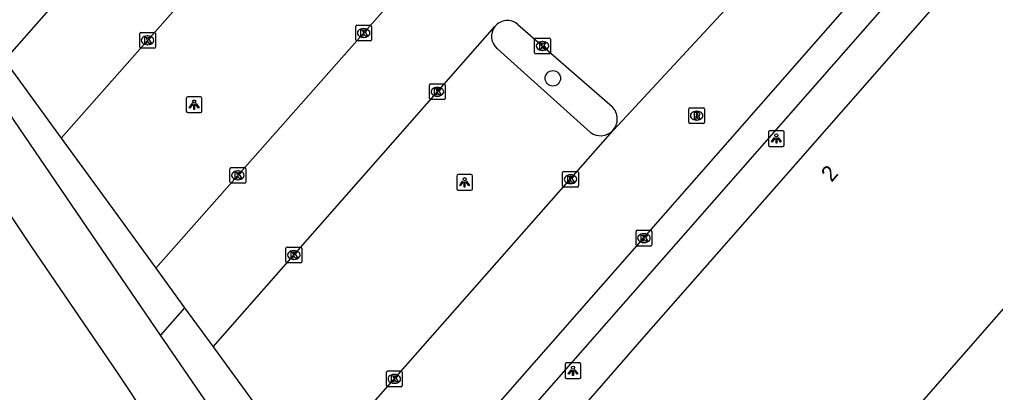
# Model space of a CAD drawing. Extents: x 158474 to 159560, y 388525 to 389605.
# Drawn here: x 158694.2 to 158756.2, y 388754.6 to 388778.3 of the extents above; entities that cross this region are included whole.
import ezdxf

# ---------------------------------------------------------------- set-up
doc = ezdxf.new("R2010")
doc.units = 0
for name, color, linetype in [('IMGEO_Boom', 7, 'Continuous'), ('IMGEO_Groenvoorziening', 7, 'Continuous'), ('IMGEO_Kolk', 7, 'Continuous'), ('IMGEO_Lichtpunt', 7, 'Continuous'), ('IMGEO_Meer_plas_ven_vijver', 7, 'Continuous'), ('IMGEO_Pand', 7, 'Continuous'), ('IMGEO_Pand_nummerreeks', 7, 'Continuous'), ('IMGEO_Parkeervlak_open', 7, 'Continuous'), ('IMGEO_Rijbaan_lokaal_open', 7, 'Continuous'), ('IMGEO_Rioolput', 7, 'Continuous'), ('IMGEO_Voetpad_open', 7, 'Continuous'), ('IMGEO_Walbescherming', 7, 'Continuous')]:
    doc.layers.add(name, color=color, linetype=linetype)

msp = doc.modelspace()

# ---------------------------------------------------------------- linework, layer by layer
at = {"layer": 'IMGEO_Boom'}
msp.add_circle((158728.062, 388774.565), 0.489, dxfattribs=at)
at = {"layer": 'IMGEO_Groenvoorziening'}
for points in [[(158703.128, 388758.224), (158699.444, 388763.626), (158691.492, 388775.285), (158687.327, 388781.391), (158681.382, 388789.641), (158676.637, 388797.026), (158667.372, 388809.99), (158665.283, 388814.769), (158660.005, 388821.203), (158657.276, 388822.984), (158656.805, 388823.409), (158654.184, 388825.806)], [(158704.66, 388759.967), (158703.128, 388758.224)], [(158714.762, 388744.037), (158714.238, 388744.412), (158711.437, 388746.785), (158708.904, 388750), (158707.649, 388751.593), (158703.128, 388758.224)]]:
    msp.add_lwpolyline(points, dxfattribs=at)
at = {"layer": 'IMGEO_Kolk'}
for p, q in [((158715.537, 388777.02), (158715.537, 388777.872)), ((158715.612, 388777.946), (158716.464, 388777.946)), ((158716.538, 388777.872), (158716.538, 388777.02)), ((158701.801, 388776.555), (158701.801, 388777.407)), ((158701.876, 388777.481), (158702.728, 388777.481)), ((158702.289, 388777.261), (158702.314, 388777.261)), ((158702.802, 388777.407), (158702.802, 388776.555)), ((158716.025, 388777.726), (158716.05, 388777.726)), ((158702.312, 388776.701), (158702.287, 388776.701)), ((158716.464, 388776.946), (158715.612, 388776.946)), ((158716.048, 388777.166), (158716.023, 388777.166)), ((158726.905, 388776.195), (158726.905, 388777.047)), ((158726.98, 388777.121), (158727.832, 388777.121)), ((158727.393, 388776.901), (158727.418, 388776.901)), ((158727.906, 388777.047), (158727.906, 388776.195)), ((158702.728, 388776.481), (158701.876, 388776.481)), ((158727.832, 388776.121), (158726.98, 388776.121)), ((158727.416, 388776.341), (158727.391, 388776.341)), ((158720.226, 388773.283), (158720.226, 388774.135)), ((158720.301, 388774.209), (158721.153, 388774.209)), ((158721.227, 388774.135), (158721.227, 388773.283)), ((158720.714, 388773.989), (158720.739, 388773.989)), ((158721.153, 388773.209), (158720.301, 388773.209)), ((158720.737, 388773.429), (158720.712, 388773.429)), ((158707.542, 388767.962), (158707.542, 388768.814)), ((158707.617, 388768.888), (158708.469, 388768.888)), ((158708.03, 388768.668), (158708.055, 388768.668)), ((158708.543, 388768.814), (158708.543, 388767.962)), ((158728.684, 388767.717), (158728.684, 388768.569)), ((158728.759, 388768.643), (158729.611, 388768.643)), ((158729.685, 388768.569), (158729.685, 388767.717)), ((158708.469, 388767.888), (158707.617, 388767.888)), ((158708.053, 388768.108), (158708.028, 388768.108)), ((158729.172, 388768.423), (158729.197, 388768.423)), ((158729.611, 388767.643), (158728.759, 388767.643)), ((158729.195, 388767.863), (158729.17, 388767.863)), ((158733.351, 388763.968), (158733.351, 388764.82)), ((158733.426, 388764.894), (158734.278, 388764.894)), ((158734.352, 388764.82), (158734.352, 388763.968)), ((158733.839, 388764.674), (158733.864, 388764.674)), ((158711.099, 388762.894), (158711.099, 388763.746)), ((158711.174, 388763.82), (158712.026, 388763.82)), ((158711.587, 388763.6), (158711.612, 388763.6)), ((158712.1, 388763.746), (158712.1, 388762.894)), ((158734.278, 388763.894), (158733.426, 388763.894)), ((158733.862, 388764.114), (158733.837, 388764.114)), ((158711.61, 388763.04), (158711.585, 388763.04)), ((158712.026, 388762.82), (158711.174, 388762.82)), ((158717.485, 388755.014), (158717.485, 388755.866)), ((158717.56, 388755.94), (158718.412, 388755.94)), ((158717.973, 388755.72), (158717.998, 388755.72)), ((158718.486, 388755.866), (158718.486, 388755.014)), ((158718.412, 388754.94), (158717.56, 388754.94)), ((158717.996, 388755.16), (158717.971, 388755.16))]:
    msp.add_line(p, q, dxfattribs=at)
for points in [[(158715.537, 388777.02), (158715.537, 388777.872)], [(158715.612, 388777.946), (158716.464, 388777.946)], [(158716.538, 388777.872), (158716.538, 388777.02)], [(158701.801, 388776.555), (158701.801, 388777.407)], [(158701.876, 388777.481), (158702.728, 388777.481)], [(158702.122, 388777.181), (158702.245, 388777.181), (158702.245, 388777.03), (158702.375, 388777.181), (158702.539, 388777.181), (158702.393, 388777.03), (158702.546, 388776.781), (158702.394, 388776.781), (158702.309, 388776.945), (158702.245, 388776.878), (158702.245, 388776.781), (158702.122, 388776.781), (158702.122, 388777.181)], [(158702.802, 388777.407), (158702.802, 388776.555)], [(158715.858, 388777.646), (158715.981, 388777.646), (158715.981, 388777.495), (158716.111, 388777.646), (158716.275, 388777.646), (158716.129, 388777.495), (158716.282, 388777.246), (158716.13, 388777.246), (158716.045, 388777.41), (158715.981, 388777.343), (158715.981, 388777.246), (158715.858, 388777.246), (158715.858, 388777.646)], [(158716.464, 388776.946), (158715.612, 388776.946)], [(158726.905, 388776.195), (158726.905, 388777.047)], [(158726.98, 388777.121), (158727.832, 388777.121)], [(158727.226, 388776.821), (158727.349, 388776.821), (158727.349, 388776.67), (158727.479, 388776.821), (158727.643, 388776.821), (158727.497, 388776.67), (158727.65, 388776.421), (158727.498, 388776.421), (158727.413, 388776.585), (158727.349, 388776.518), (158727.349, 388776.421), (158727.226, 388776.421), (158727.226, 388776.821)], [(158727.906, 388777.047), (158727.906, 388776.195)], [(158702.728, 388776.481), (158701.876, 388776.481)], [(158727.832, 388776.121), (158726.98, 388776.121)], [(158720.226, 388773.283), (158720.226, 388774.135)], [(158720.301, 388774.209), (158721.153, 388774.209)], [(158721.227, 388774.135), (158721.227, 388773.283)], [(158720.547, 388773.909), (158720.67, 388773.909), (158720.67, 388773.758), (158720.8, 388773.909), (158720.964, 388773.909), (158720.818, 388773.758), (158720.971, 388773.509), (158720.819, 388773.509), (158720.734, 388773.673), (158720.67, 388773.606), (158720.67, 388773.509), (158720.547, 388773.509), (158720.547, 388773.909)], [(158721.153, 388773.209), (158720.301, 388773.209)], [(158707.542, 388767.962), (158707.542, 388768.814)], [(158707.617, 388768.888), (158708.469, 388768.888)], [(158707.863, 388768.588), (158707.986, 388768.588), (158707.986, 388768.437), (158708.116, 388768.588), (158708.28, 388768.588), (158708.134, 388768.437), (158708.287, 388768.188), (158708.135, 388768.188), (158708.05, 388768.352), (158707.986, 388768.285), (158707.986, 388768.188), (158707.863, 388768.188), (158707.863, 388768.588)], [(158708.543, 388768.814), (158708.543, 388767.962)], [(158728.684, 388767.717), (158728.684, 388768.569)], [(158728.759, 388768.643), (158729.611, 388768.643)], [(158729.685, 388768.569), (158729.685, 388767.717)], [(158708.469, 388767.888), (158707.617, 388767.888)], [(158729.005, 388768.343), (158729.128, 388768.343), (158729.128, 388768.192), (158729.258, 388768.343), (158729.422, 388768.343), (158729.276, 388768.192), (158729.429, 388767.943), (158729.277, 388767.943), (158729.192, 388768.107), (158729.128, 388768.04), (158729.128, 388767.943), (158729.005, 388767.943), (158729.005, 388768.343)], [(158729.611, 388767.643), (158728.759, 388767.643)], [(158733.351, 388763.968), (158733.351, 388764.82)], [(158733.426, 388764.894), (158734.278, 388764.894)], [(158734.352, 388764.82), (158734.352, 388763.968)], [(158733.672, 388764.594), (158733.795, 388764.594), (158733.795, 388764.443), (158733.925, 388764.594), (158734.089, 388764.594), (158733.943, 388764.443), (158734.096, 388764.194), (158733.944, 388764.194), (158733.859, 388764.358), (158733.795, 388764.291), (158733.795, 388764.194), (158733.672, 388764.194), (158733.672, 388764.594)], [(158711.099, 388762.894), (158711.099, 388763.746)], [(158711.174, 388763.82), (158712.026, 388763.82)], [(158712.1, 388763.746), (158712.1, 388762.894)], [(158734.278, 388763.894), (158733.426, 388763.894)], [(158711.42, 388763.52), (158711.543, 388763.52), (158711.543, 388763.369), (158711.673, 388763.52), (158711.837, 388763.52), (158711.691, 388763.369), (158711.844, 388763.12), (158711.692, 388763.12), (158711.607, 388763.284), (158711.543, 388763.217), (158711.543, 388763.12), (158711.42, 388763.12), (158711.42, 388763.52)], [(158712.026, 388762.82), (158711.174, 388762.82)], [(158717.485, 388755.014), (158717.485, 388755.866)], [(158717.56, 388755.94), (158718.412, 388755.94)], [(158717.806, 388755.64), (158717.929, 388755.64), (158717.929, 388755.489), (158718.059, 388755.64), (158718.223, 388755.64), (158718.077, 388755.489), (158718.23, 388755.24), (158718.078, 388755.24), (158717.993, 388755.404), (158717.929, 388755.337), (158717.929, 388755.24), (158717.806, 388755.24), (158717.806, 388755.64)], [(158718.486, 388755.866), (158718.486, 388755.014)], [(158718.412, 388754.94), (158717.56, 388754.94)]]:
    msp.add_lwpolyline(points, dxfattribs=at)
for centre, start, end in [((158715.614, 388777.87), 91.55205, 178.44795), ((158715.614, 388777.87), 91.55205, 178.44795), ((158716.462, 388777.87), 1.55205, 88.44795), ((158716.462, 388777.87), 1.55205, 88.44795), ((158701.878, 388777.405), 91.55205, 178.44795), ((158701.878, 388777.405), 91.55205, 178.44795), ((158702.726, 388777.405), 1.55205, 88.44795), ((158702.726, 388777.405), 1.55205, 88.44795), ((158701.878, 388776.557), 181.55205, 268.44795), ((158701.878, 388776.557), 181.55205, 268.44795), ((158702.726, 388776.557), 271.55205, 358.44795), ((158702.726, 388776.557), 271.55205, 358.44795), ((158715.614, 388777.022), 181.55205, 268.44795), ((158715.614, 388777.022), 181.55205, 268.44795), ((158716.462, 388777.022), 271.55205, 358.44795), ((158716.462, 388777.022), 271.55205, 358.44795), ((158726.982, 388777.045), 91.55205, 178.44795), ((158726.982, 388777.045), 91.55205, 178.44795), ((158727.83, 388777.045), 1.55205, 88.44795), ((158727.83, 388777.045), 1.55205, 88.44795), ((158726.982, 388776.197), 181.55205, 268.44795), ((158726.982, 388776.197), 181.55205, 268.44795), ((158727.83, 388776.197), 271.55205, 358.44795), ((158727.83, 388776.197), 271.55205, 358.44795), ((158720.303, 388774.133), 91.55205, 178.44795), ((158720.303, 388774.133), 91.55205, 178.44795), ((158721.151, 388774.133), 1.55205, 88.44795), ((158721.151, 388774.133), 1.55205, 88.44795), ((158720.303, 388773.285), 181.55205, 268.44795), ((158720.303, 388773.285), 181.55205, 268.44795), ((158721.151, 388773.285), 271.55205, 358.44795), ((158721.151, 388773.285), 271.55205, 358.44795), ((158707.619, 388768.812), 91.55205, 178.44795), ((158707.619, 388768.812), 91.55205, 178.44795), ((158708.467, 388768.812), 1.55205, 88.44795), ((158708.467, 388768.812), 1.55205, 88.44795), ((158728.761, 388768.567), 91.55205, 178.44795), ((158728.761, 388768.567), 91.55205, 178.44795), ((158729.609, 388768.567), 1.55205, 88.44795), ((158729.609, 388768.567), 1.55205, 88.44795), ((158707.619, 388767.964), 181.55205, 268.44795), ((158707.619, 388767.964), 181.55205, 268.44795), ((158708.467, 388767.964), 271.55205, 358.44795), ((158708.467, 388767.964), 271.55205, 358.44795), ((158728.761, 388767.719), 181.55205, 268.44795), ((158728.761, 388767.719), 181.55205, 268.44795), ((158729.609, 388767.719), 271.55205, 358.44795), ((158729.609, 388767.719), 271.55205, 358.44795), ((158733.428, 388764.818), 91.55205, 178.44795), ((158733.428, 388764.818), 91.55205, 178.44795), ((158734.276, 388764.818), 1.55205, 88.44795), ((158734.276, 388764.818), 1.55205, 88.44795), ((158711.176, 388763.744), 91.55205, 178.44795), ((158711.176, 388763.744), 91.55205, 178.44795), ((158712.024, 388763.744), 1.55205, 88.44795), ((158712.024, 388763.744), 1.55205, 88.44795), ((158733.428, 388763.97), 181.55205, 268.44795), ((158733.428, 388763.97), 181.55205, 268.44795), ((158734.276, 388763.97), 271.55205, 358.44795), ((158734.276, 388763.97), 271.55205, 358.44795), ((158711.176, 388762.896), 181.55205, 268.44795), ((158711.176, 388762.896), 181.55205, 268.44795), ((158712.024, 388762.896), 271.55205, 358.44795), ((158712.024, 388762.896), 271.55205, 358.44795), ((158717.562, 388755.864), 91.55205, 178.44795), ((158717.562, 388755.864), 91.55205, 178.44795), ((158718.41, 388755.864), 1.55205, 88.44795), ((158718.41, 388755.864), 1.55205, 88.44795), ((158717.562, 388755.016), 181.55205, 268.44795), ((158717.562, 388755.016), 181.55205, 268.44795), ((158718.41, 388755.016), 271.55205, 358.44795), ((158718.41, 388755.016), 271.55205, 358.44795)]:
    msp.add_arc(centre, 0.0765, start, end, dxfattribs=at)
for centre, major_axis, ratio, start_param, end_param in [((158702.288, 388776.981), (-0.387, 0.002), 0.722429, 4.712389, 7.853982), ((158702.313, 388776.981), (-0.39, 0.002), 0.717154, 1.570796, 4.712389), ((158716.024, 388777.446), (-0.387, 0.002), 0.722429, 4.712389, 7.853982), ((158716.049, 388777.446), (-0.39, 0.002), 0.717154, 1.570796, 4.712389), ((158727.392, 388776.621), (-0.387, 0.002), 0.722429, 4.712389, 7.853982), ((158727.417, 388776.621), (-0.39, 0.002), 0.717154, 1.570796, 4.712389), ((158720.713, 388773.709), (-0.387, 0.002), 0.722429, 4.712389, 7.853982), ((158720.738, 388773.709), (-0.39, 0.002), 0.717154, 1.570796, 4.712389), ((158708.029, 388768.388), (-0.387, 0.002), 0.722429, 4.712389, 7.853982), ((158708.054, 388768.388), (-0.39, 0.002), 0.717154, 1.570796, 4.712389), ((158729.171, 388768.143), (-0.387, 0.002), 0.722429, 4.712389, 7.853982), ((158729.196, 388768.143), (-0.39, 0.002), 0.717154, 1.570796, 4.712389), ((158733.838, 388764.394), (-0.387, 0.002), 0.722429, 4.712389, 7.853982), ((158733.863, 388764.394), (-0.39, 0.002), 0.717154, 1.570796, 4.712389), ((158711.586, 388763.32), (-0.387, 0.002), 0.722429, 4.712389, 7.853982), ((158711.611, 388763.32), (-0.39, 0.002), 0.717154, 1.570796, 4.712389), ((158717.972, 388755.44), (-0.387, 0.002), 0.722429, 4.712389, 7.853982), ((158717.997, 388755.44), (-0.39, 0.002), 0.717154, 1.570796, 4.712389)]:
    msp.add_ellipse(centre, major_axis=major_axis, ratio=ratio, start_param=start_param, end_param=end_param, dxfattribs=at)
at = {"layer": 'IMGEO_Lichtpunt'}
for p, q in [((158704.763, 388773.289), (158704.763, 388772.482)), ((158704.763, 388773.289), (158704.763, 388772.482)), ((158705.665, 388773.384), (158704.857, 388773.384)), ((158705.665, 388773.384), (158704.857, 388773.384)), ((158705.759, 388772.482), (158705.759, 388773.289)), ((158705.759, 388772.482), (158705.759, 388773.289)), ((158704.857, 388772.388), (158705.665, 388772.388)), ((158704.857, 388772.388), (158705.665, 388772.388)), ((158741.77, 388771.137), (158741.77, 388770.33)), ((158741.77, 388771.137), (158741.77, 388770.33)), ((158742.672, 388771.232), (158741.864, 388771.232)), ((158742.672, 388771.232), (158741.864, 388771.232)), ((158742.766, 388770.33), (158742.766, 388771.137)), ((158742.766, 388770.33), (158742.766, 388771.137)), ((158741.864, 388770.236), (158742.672, 388770.236)), ((158741.864, 388770.236), (158742.672, 388770.236)), ((158721.955, 388768.348), (158721.955, 388767.541)), ((158721.955, 388768.348), (158721.955, 388767.541)), ((158722.857, 388768.443), (158722.049, 388768.443)), ((158722.857, 388768.443), (158722.049, 388768.443)), ((158722.951, 388767.541), (158722.951, 388768.348)), ((158722.951, 388767.541), (158722.951, 388768.348)), ((158722.049, 388767.447), (158722.857, 388767.447)), ((158722.049, 388767.447), (158722.857, 388767.447)), ((158728.846, 388756.358), (158728.846, 388755.551)), ((158728.846, 388756.358), (158728.846, 388755.551)), ((158729.748, 388756.453), (158728.94, 388756.453)), ((158729.748, 388756.453), (158728.94, 388756.453)), ((158729.842, 388755.551), (158729.842, 388756.358)), ((158729.842, 388755.551), (158729.842, 388756.358)), ((158728.94, 388755.457), (158729.748, 388755.457)), ((158728.94, 388755.457), (158729.748, 388755.457))]:
    msp.add_line(p, q, dxfattribs=at)
for points in [[(158705.137, 388772.953), (158705.176, 388772.925), (158704.988, 388772.663), (158704.95, 388772.69), (158705.137, 388772.953)], [(158705.239, 388772.905), (158705.286, 388772.905), (158705.286, 388772.583), (158705.239, 388772.583), (158705.239, 388772.905)], [(158705.349, 388772.925), (158705.387, 388772.952), (158705.574, 388772.69), (158705.535, 388772.662), (158705.349, 388772.925)], [(158742.144, 388770.801), (158742.183, 388770.773), (158741.995, 388770.511), (158741.957, 388770.538), (158742.144, 388770.801)], [(158742.246, 388770.753), (158742.293, 388770.753), (158742.293, 388770.431), (158742.246, 388770.431), (158742.246, 388770.753)], [(158742.356, 388770.773), (158742.394, 388770.8), (158742.581, 388770.538), (158742.542, 388770.51), (158742.356, 388770.773)], [(158722.329, 388768.012), (158722.368, 388767.984), (158722.18, 388767.722), (158722.142, 388767.749), (158722.329, 388768.012)], [(158722.431, 388767.964), (158722.478, 388767.964), (158722.478, 388767.642), (158722.431, 388767.642), (158722.431, 388767.964)], [(158722.541, 388767.984), (158722.579, 388768.011), (158722.766, 388767.749), (158722.727, 388767.721), (158722.541, 388767.984)], [(158729.22, 388756.022), (158729.259, 388755.994), (158729.071, 388755.732), (158729.033, 388755.759), (158729.22, 388756.022)], [(158729.322, 388755.974), (158729.369, 388755.974), (158729.369, 388755.652), (158729.322, 388755.652), (158729.322, 388755.974)], [(158729.432, 388755.994), (158729.47, 388756.021), (158729.657, 388755.759), (158729.618, 388755.731), (158729.432, 388755.994)]]:
    msp.add_lwpolyline(points, dxfattribs=at)
for centre in [(158705.262, 388773.087), (158742.269, 388770.935), (158722.454, 388768.146), (158729.345, 388756.156)]:
    msp.add_circle(centre, 0.0994, dxfattribs=at)
for centre, start, end in [((158704.857, 388773.289), 90, 180), ((158704.857, 388773.289), 90, 180), ((158705.665, 388773.289), 0, 90), ((158705.665, 388773.289), 0, 90), ((158704.857, 388772.482), 180, 270), ((158704.857, 388772.482), 180, 270), ((158705.665, 388772.482), 270, 0), ((158705.665, 388772.482), 270, 360), ((158741.864, 388771.137), 90, 180), ((158741.864, 388771.137), 90, 180), ((158742.672, 388771.137), 0, 90), ((158742.672, 388771.137), 0, 90), ((158741.864, 388770.33), 180, 270), ((158741.864, 388770.33), 180, 270), ((158742.672, 388770.33), 270, 0), ((158742.672, 388770.33), 270, 360), ((158722.049, 388768.348), 90, 180), ((158722.049, 388768.348), 90, 180), ((158722.857, 388768.348), 0, 90), ((158722.857, 388768.348), 0, 90), ((158722.049, 388767.541), 180, 270), ((158722.049, 388767.541), 180, 270), ((158722.857, 388767.541), 270, 0), ((158722.857, 388767.541), 270, 360), ((158728.94, 388756.358), 90, 180), ((158728.94, 388756.358), 90, 180), ((158729.748, 388756.358), 0, 90), ((158729.748, 388756.358), 0, 90), ((158728.94, 388755.551), 180, 270), ((158728.94, 388755.551), 180, 270), ((158729.748, 388755.551), 270, 0), ((158729.748, 388755.551), 270, 360)]:
    msp.add_arc(centre, 0.0946, start, end, dxfattribs=at)
at = {"layer": 'IMGEO_Meer_plas_ven_vijver'}
msp.add_lwpolyline([(158784.665, 388723.576), (158750.297, 388730.833), (158739.431, 388733.025), (158727.341, 388735.59), (158714.754, 388739.311), (158711.338, 388741.806), (158702.489, 388752.682), (158700.382, 388755.839), (158694.933, 388763.87), (158675.748, 388792.648)], dxfattribs=at)
at = {"layer": 'IMGEO_Pand'}
for points in [[(158727.187, 388750.436), (158733.866, 388758.112), (158737.722, 388762.513), (158756.867, 388784.38)], [(158757.448, 388760.766), (158748.034, 388750), (158740.394, 388741.262), (158740.154, 388741.469), (158740.487, 388741.882), (158740.119, 388742.2), (158738.475, 388741.889), (158736.803, 388741.983), (158735.232, 388742.497), (158733.823, 388743.48), (158732.698, 388744.749), (158732.002, 388746.171), (158729.285, 388745.285), (158729.434, 388744.83), (158729.098, 388744.72), (158727.333, 388750), (158727.187, 388750.436)]]:
    msp.add_lwpolyline(points, dxfattribs=at)
at = {"layer": 'IMGEO_Parkeervlak_open'}
for points in [[(158724.534, 388776.45), (158730.466, 388771.111)], [(158696.814, 388770.761), (158700.24, 388766.047), (158702.831, 388762.483)], [(158706.468, 388757.48), (158711.905, 388750), (158712.481, 388749.198)]]:
    msp.add_lwpolyline(points, dxfattribs=at)
for centre, radius, start, end in [((158725.172, 388777.234), 1.011, 142.08119, 230.83189), ((158731.089, 388771.983), 1.071, 234.46074, 314.83251)]:
    msp.add_arc(centre, radius, start, end, dxfattribs=at)
at = {"layer": 'IMGEO_Rijbaan_lokaal_open'}
for points in [[(158719.735, 388748.381), (158721.191, 388750), (158721.552, 388750.402), (158777.609, 388814.378)], [(158693.219, 388775.707), (158707.784, 388792.295)], [(158711.638, 388787.571), (158696.814, 388770.761)], [(158702.831, 388762.483), (158719.16, 388781.012)], [(158739.534, 388779.487), (158731.932, 388771.294), (158731.844, 388771.223)], [(158706.468, 388757.48), (158724.375, 388777.855)], [(158725.835, 388777.996), (158731.824, 388772.762)], [(158693.219, 388775.707), (158693.274, 388775.631), (158695.007, 388773.247), (158696.814, 388770.761)], [(158731.844, 388771.223), (158713.19, 388750), (158712.481, 388749.198)], [(158702.831, 388762.483), (158704.66, 388759.967)], [(158704.66, 388759.967), (158706.468, 388757.48)]]:
    msp.add_lwpolyline(points, dxfattribs=at)
for centre, radius, start, end in [((158725.172, 388777.232), 1.011, 49.03734, 141.99516), ((158731.089, 388771.983), 1.071, 314.82405, 46.66504)]:
    msp.add_arc(centre, radius, start, end, dxfattribs=at)
at = {"layer": 'IMGEO_Rioolput'}
for p, q in [((158736.703, 388771.762), (158736.703, 388772.614)), ((158736.778, 388772.688), (158737.63, 388772.688)), ((158737.191, 388772.468), (158737.216, 388772.468)), ((158737.704, 388772.614), (158737.704, 388771.762)), ((158737.63, 388771.688), (158736.778, 388771.688)), ((158737.214, 388771.908), (158737.189, 388771.908))]:
    msp.add_line(p, q, dxfattribs=at)
for points in [[(158736.703, 388771.762), (158736.703, 388772.614)], [(158736.778, 388772.688), (158737.63, 388772.688)], [(158737.292, 388772.386), (158737.04, 388772.388), (158737.04, 388771.988)], [(158737.218, 388772.307), (158737.164, 388772.307), (158737.164, 388772.226)], [(158737.164, 388772.226), (158737.216, 388772.226)], [(158737.704, 388772.614), (158737.704, 388771.762)], [(158737.63, 388771.688), (158736.778, 388771.688)], [(158737.04, 388771.988), (158737.164, 388771.988), (158737.164, 388772.15), (158737.175, 388772.15)], [(158737.222, 388772.121), (158737.293, 388771.988), (158737.433, 388771.988), (158737.368, 388772.114)]]:
    msp.add_lwpolyline(points, dxfattribs=at)
for centre, radius, start, end in [((158736.78, 388772.612), 0.0765, 91.55205, 178.44795), ((158736.78, 388772.612), 0.0765, 91.55205, 178.44795), ((158737.2, 388772.415), 0.19, 274.7715, 282.96867), ((158737.224, 388772.211), 0.0964, 77.00612, 93.18647), ((158737.238, 388772.268), 0.0378, 276.66336, 79.67722), ((158737.291, 388772.276), 0.109, 350.36119, 89.41601), ((158737.289, 388772.276), 0.112, 277.58423, 350.98172), ((158737.628, 388772.612), 0.0765, 1.55205, 88.44795), ((158737.628, 388772.612), 0.0765, 1.55205, 88.44795), ((158736.78, 388771.764), 0.0765, 181.55205, 268.44795), ((158736.78, 388771.764), 0.0765, 181.55205, 268.44795), ((158737.174, 388772.097), 0.0533, 26.02933, 88.69889), ((158737.273, 388772.061), 0.108, 29.51342, 73.79051), ((158737.628, 388771.764), 0.0765, 271.55205, 358.44795), ((158737.628, 388771.764), 0.0765, 271.55205, 358.44795)]:
    msp.add_arc(centre, radius, start, end, dxfattribs=at)
for centre, major_axis, ratio, start_param, end_param in [((158737.19, 388772.188), (-0.387, 0.002), 0.722429, 4.712389, 7.853982), ((158737.215, 388772.188), (-0.39, 0.002), 0.717154, 1.570796, 4.712389)]:
    msp.add_ellipse(centre, major_axis=major_axis, ratio=ratio, start_param=start_param, end_param=end_param, dxfattribs=at)
at = {"layer": 'IMGEO_Voetpad_open'}
msp.add_lwpolyline([(158779.391, 388813.69), (158724.917, 388751.537), (158723.574, 388750), (158723.072, 388749.425)], dxfattribs=at)
at = {"layer": 'IMGEO_Walbescherming'}
msp.add_lwpolyline([(158700.382, 388755.839), (158694.933, 388763.87)], dxfattribs=at)

# ---------------------------------------------------------------- texts
at = {"layer": 'IMGEO_Pand_nummerreeks'}
msp.add_text('2', height=1, rotation=48.7972, dxfattribs=at).set_placement((158745.774, 388767.914))

doc.saveas('drawing.dxf')
